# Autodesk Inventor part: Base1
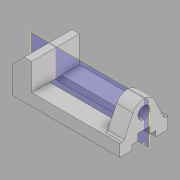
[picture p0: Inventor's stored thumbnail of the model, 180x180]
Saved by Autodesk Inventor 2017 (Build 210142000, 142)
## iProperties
Created: 2016-03
Part Number: Base1
Material: Generic
Document SubType Name: Modeling
Designer: Sandeep
Density: 1 g/cm^3
Appearance: Default
Author: Sandeep
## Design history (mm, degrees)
sketch "Sketch1"
  geometry: L1 (0, 0)-(0, 16); L2 (0, 16)-(118, 16); L3 (118, 16)-(118, 52); L4 (118, 52)-(144, 52); L5 (144, 52)-(144, 0); L6 (144, 0)-(0, 0)
  constraints: 12 end point, 3 perpendicular, 1 vertical
  dimensions: "d1" = 144 distance of L5.end L1.start; "d2" = 26 distance of L3.end L4.end; "d3" = 16 distance between parallel lines of L6 L2; "d4" = 36 distance between parallel lines of L2 L4
extrude "Extrusion1" new body sketch "Sketch1" stored distance "d5" = 64; taper "d6" = 0 deg
chamfer "Chamfer1" distance "d7" = 16; stored, may be unused: second distance "d8" = 16, angle "d9" = 45 deg
sketch "Sketch4"
  geometry: 1 further point
sketch "Sketch5"
  geometry: L1 (-16, 5.02)-(-42.762, 17.499); L2 (-42.762, 46.501)-(-16, 58.98); L3 (-52, 64)-(-52, 0) reference; L4 (-16, 32)-(-54.774, 32); L5 (-52, 64)-(-16, 64) reference; L6 (-16, 64)-(-16, 0) reference; L7 (-16, 5.02)-(-16, 58.98); L8 (0, 64)-(0, 0) reference; A1 r 16 centre (-36, 32) between (-42.762, 46.501) and (-42.762, 17.499); 1 further point
  constraints: 8 end point, 3 point on line, 3 tangent, 2 point on circle, 1 centre point, 1 collinear, 1 horizontal, 1 other
  dimensions: "d21" = 50 deg angle of L2 L1; "d22" = 36 distance from line of L8 A1.centre
extrude "Extrusion2" join sketch "Sketch5" distance "d23" = 22; taper "d24" = 0 deg
fillet "Fillet1" dims "d25" = 3
sketch "Sketch6"
  geometry: L1 (-36, 64)-(-36, 0) reference; C1 r 8 at (-36, 32); A1 r 16 centre (-36, 32) between (-42.762, 46.501) and (-42.762, 17.499) reference; 1 further point
  constraints: 1 centre point, 1 concentric, 1 midpoint
  dimensions: "d26" = 16 diameter of C1
extrude "Extrusion3" cut sketch "Sketch6" distance "d27" = 22; taper "d28" = 0 deg
sketch "Sketch7"
  geometry: L1 (0, 0)-(0, 64) reference; L2 (0, 16)-(-7, 16); L3 (-7, 16)-(-7, 24); L4 (-7, 24)-(-16, 24); L5 (-16, 3.109)-(-16, 60.891) reference; L6 (-16, 24)-(-16, 40); L7 (-7, 40)-(-7, 48); L8 (-7, 48)-(0, 48); L9 (0, 48)-(0, 16); L10 (-7, 40)-(-16, 40); L11 (-44, 32)-(-36, 32); 1 further point
  constraints: 18 end point, 6 point on line, 4 perpendicular, 2 horizontal, 1 collinear, 1 horizontal alignment, 4 other
  dimensions: "d29" = 32 distance between parallel lines of L2 L8; "d30" = 7 distance of L7.end L8.end; "d45" = 16 distance between parallel lines of L10 L4
extrude "Extrusion4" cut sketch "Sketch7" distance "d31" = 167.75; taper "d32" = 0 deg
sketch "Sketch8"
  geometry: L1 (144, 0)-(144, -16) reference; L2 (0, 0)-(144, 0) reference; L3 (0, -16)-(0, 0) reference; 3 further points
  dimensions: "d33" = 70 distance of point (108, -10) point (38, -10); "d35" = 10 distance from line of L2 point (108, -10); "d36" = 10 distance from line of L2 point (38, -10); "d46" = 38 distance from line of L3 point (38, -10)
hole "Hole1" sketch "Sketch8" at (38, -10), (108, -10) diameter "d37" = 4.917; stored, may be unused: countersink angle "d41" = 90 deg, drill point angle "d43" = 118 deg; dims "d38" = 12, "d39" = 4, "d40" = 2, "d42" = 10
workplane "Work Plane1"
mirror "Mirror1"
body "Solid1"
other parameters: "d10" = 16, "d13" = 7, "d14" = 16, "d44" = -32
